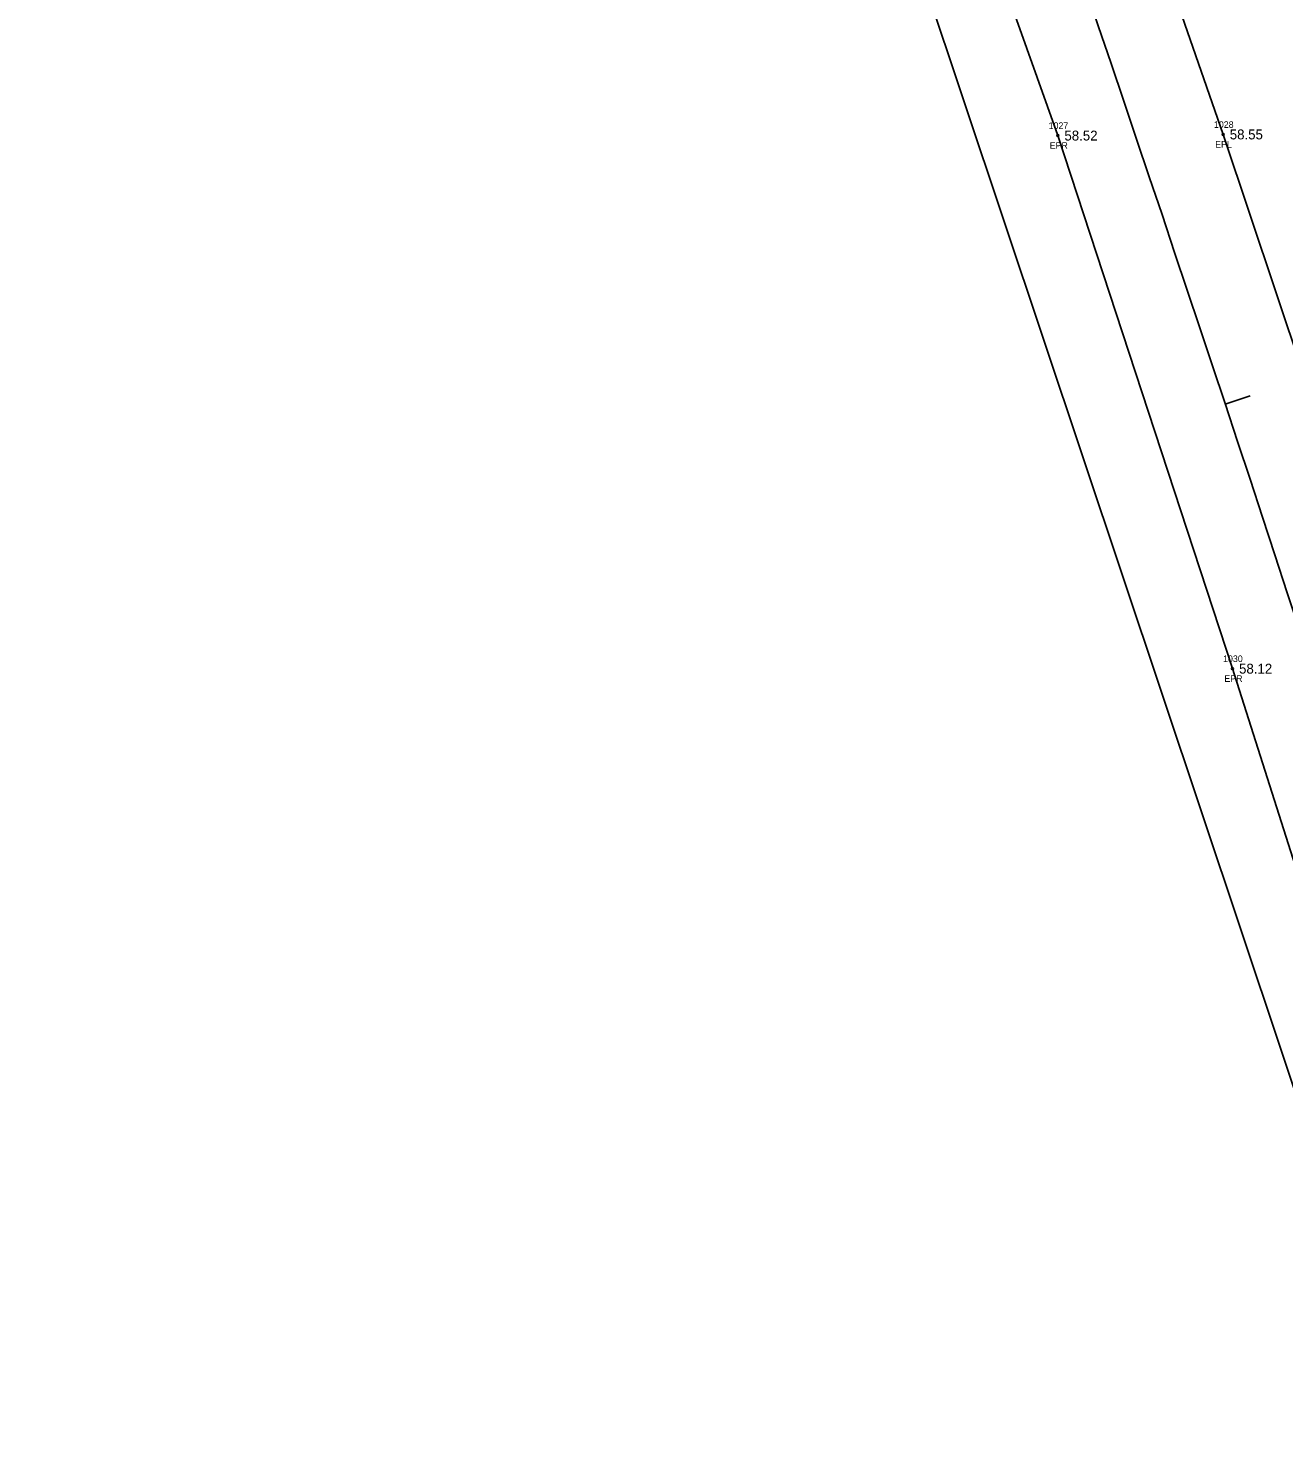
# Model space of a CAD drawing. Extents: x 2396531 to 2397633, y 770203 to 772837.
# Drawn here: x 2396658.8 to 2396848.8, y 771981.7 to 772197.8 of the extents above; entities that cross this region are included whole.
import ezdxf

# ---------------------------------------------------------------- set-up
doc = ezdxf.new("R2010")
doc.units = 0
for name, color, linetype in [('RD_EX_Road', 7, 'Continuous'), ('RD_EX_Road_txCode', 7, 'Continuous'), ('RD_EX_TX_Road_ELEV', 7, 'Continuous'), ('RD_EX_VEG', 7, 'Continuous'), ('RD_HC_Cl', 7, 'Continuous'), ('RD_HC_Data_Tic', 7, 'Continuous'), ('RD_SMD_Locator', 7, 'Continuous')]:
    doc.layers.add(name, color=color, linetype=linetype)

msp = doc.modelspace()

# ---------------------------------------------------------------- linework, layer by layer
at = {"layer": 'RD_EX_Road'}
for points in [[(2396680.92, 772617.84), (2396715.6, 772525.73), (2396750.68, 772430.62), (2396786.3, 772332.21), (2396811.38, 772263.31), (2396839.69, 772181.74), (2396863.75, 772109.83), (2396883.63, 772046.56), (2396889.54, 772027.11), (2396896.25, 772004.37), (2396904.34, 771978.33), (2396908.24, 771964.89), (2396921.74, 771919.68), (2396927.03, 771902.11), (2396950.2, 771821.74), (2396970.47, 771750.68), (2396978.33, 771721.29), (2396990.58, 771675.04), (2397004.94, 771620.49), (2397034.26, 771508.8), (2397061.11, 771410.49), (2397060.64, 771407.04), (2397062.07, 771407.67)], [(2396658.78, 772611.07), (2396693.37, 772516.9), (2396729.65, 772418.78), (2396760.7, 772333.11), (2396788.58, 772254.87), (2396814.65, 772181.57), (2396841.1, 772100.86), (2396861.19, 772037.76), (2396886.09, 771955.71), (2396907.15, 771884.49), (2396928.56, 771811.72), (2396947.65, 771744.09), (2396985.17, 771602.64), (2397011.11, 771504.04), (2397037.95, 771404.25), (2397039, 771401.22)]]:
    msp.add_lwpolyline(points, dxfattribs=at)
at = {"layer": 'RD_EX_VEG'}
msp.add_lwpolyline([(2396666.35, 772324.52), (2396746.5, 772348.13), (2396878.43, 771953.6), (2396907.83, 771806.94), (2396910.04, 771736.08), (2396945.43, 771592.11), (2397049.51, 771229.15), (2396980.16, 771221.67)], dxfattribs=at)
at = {"layer": 'RD_HC_Cl'}
msp.add_arc((2389304.02, 769643.48), 7939.03, 14.59125, 20.164785, dxfattribs=at)
at = {"layer": 'RD_HC_Data_Tic'}
msp.add_line((2396840, 772140.93), (2396843.8, 772142.19), dxfattribs=at)
at = {"layer": 'RD_SMD_Locator'}
for centre in [(2396814.65, 772181.57), (2396839.69, 772181.74), (2396841.1, 772100.86)]:
    msp.add_circle(centre, 0.15, dxfattribs=at)

# ---------------------------------------------------------------- texts
at = {"layer": 'RD_EX_Road_txCode'}
for s, p in [('1027', (2396813.26, 772182.57)), ('1028', (2396838.3, 772182.74)), ('EPR', (2396813.42, 772179.57)), ('EPL', (2396838.48, 772179.74)), ('1030', (2396839.68, 772101.86)), ('EPR', (2396839.87, 772098.86))]:
    msp.add_text(s, height=1, dxfattribs=at).set_placement(p)
at = {"layer": 'RD_EX_TX_Road_ELEV'}
for s, p in [('58.52', (2396815.65, 772180.82)), ('58.55', (2396840.69, 772180.99)), ('58.12', (2396842.1, 772100.11))]:
    msp.add_text(s, height=1.5, dxfattribs=at).set_placement(p)

doc.saveas('drawing.dxf')
